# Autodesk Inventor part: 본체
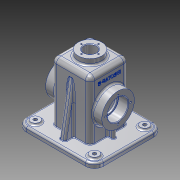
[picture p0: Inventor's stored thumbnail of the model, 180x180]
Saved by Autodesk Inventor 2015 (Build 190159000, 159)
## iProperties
Created: 2016-02
Part Number: 본체
Material: 알루미늄 6061
Document SubType Name: Modeling
Designer: Administrator
Density: 2.7 g/cm^3
Appearance: 알루미늄 - 평지
Mass: 783.394 g
Surface Area: 909.509 cm^2
Volume: 290.146 cm^3
Author: Administrator
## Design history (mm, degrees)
sketch "스케치1"
  geometry: L1 (-65, -57.5)-(65, -57.5); L2 (65, -57.5)-(65, 57.5); L3 (65, 57.5)-(-65, 57.5); L4 (-65, 57.5)-(-65, -57.5); 3 further points
  constraints: 8 end point, 2 midpoint, 2 parallel, 1 horizontal, 1 horizontal alignment, 1 perpendicular, 1 vertical alignment
  dimensions: "d0" = 130 distance of L2.end L3.end; "d1" = 115 distance of L1.end L2.end
extrude "돌출1" new body sketch "스케치1" distance "d2" = 8; taper "d3" = 0 deg
sketch "스케치2"
  geometry: L1 (-60, -52.5)-(60, -52.5); L2 (60, -52.5)-(60, 52.5); L3 (60, 52.5)-(-60, 52.5); L4 (-60, 52.5)-(-60, -52.5); 3 further points
  constraints: 8 end point, 2 midpoint, 2 parallel, 1 horizontal, 1 horizontal alignment, 1 perpendicular, 1 vertical alignment
  dimensions: "d4" = 105 distance of L3.end L1.start; "d5" = 120 distance of L2.end L3.end
extrude "돌출2" join sketch "스케치2" distance "d6" = 2; taper "d7" = 0 deg
sketch "스케치3"
  geometry: L1 (-32.5, -32.5)-(32.5, -32.5); L2 (32.5, -32.5)-(32.5, 32.5); L3 (32.5, 32.5)-(-32.5, 32.5); L4 (-32.5, 32.5)-(-32.5, -32.5); 3 further points
  constraints: 8 end point, 2 midpoint, 2 parallel, 1 horizontal, 1 horizontal alignment, 1 perpendicular, 1 vertical alignment
  dimensions: "d8" = 65 distance of L2.end L3.end; "d9" = 65 distance of L1.end L2.end
extrude "돌출3" join sketch "스케치3" distance "d10" = 100; taper "d11" = 0 deg
sketch "스케치4"
  geometry: L1 (27.5, -27.5)-(-27.5, -27.5); L2 (-27.5, -27.5)-(-27.5, 27.5); L3 (-27.5, 27.5)-(27.5, 27.5); L4 (27.5, 27.5)-(27.5, -27.5); 3 further points
  constraints: 8 end point, 2 midpoint, 2 parallel, 1 horizontal, 1 horizontal alignment, 1 perpendicular, 1 vertical alignment
  dimensions: "d12" = 55 distance of L1.end L2.end; "d13" = 55 distance of L2.end L3.end
extrude "돌출4" cut sketch "스케치4" distance "d14" = 105; taper "d15" = 0 deg
sketch "스케치5"
  geometry: C1 r 20 at (0, 0); 1 further point
  constraints: 1 centre point, 1 coincident
  dimensions: "d16" = 40 diameter of C1
extrude "돌출5" join sketch "스케치5" distance "d17" = 10; taper "d18" = 0 deg
hole "구멍1" diameter "d21" = 21; stored, may be unused: countersink angle "d25" = 90 deg, drill point angle "d27" = 118 deg; dims "d19" = 10, "d20" = 10, "d22" = 6, "d23" = 4, "d24" = 2, "d26" = 8
sketch "스케치7"
  geometry: C1 r 10.5 at (0, 0) reference; C2 r 20 at (0, 0) reference; 5 further points
  constraints: 2 horizontal alignment, 2 vertical alignment
  dimensions: "d28" = 14.5 distance of point (-14.5, 0) point (0, 0); "d29" = 14.5 distance of point (0, 0) point (0, 14.5); "d30" = 14.5 distance of point (0, 0) point (14.5, 0); "d31" = 14.5 distance of point (0, 0) point (0, -14.5)
hole "구멍2" sketch "스케치7" at (-14.5, 0), (0, 14.5), (14.5, 0), (0, -14.5) diameter "d32" = 2.459; stored, may be unused: countersink angle "d36" = 90 deg, drill point angle "d38" = 118 deg; dims "d33" = 7, "d34" = 4, "d35" = 2, "d37" = 9
fillet "모깎기1" dims "d43" = 15
sketch "스케치9"
  geometry: L1 (-50, 57.5)-(50, 57.5) reference; L2 (65, 42.5)-(65, -42.5) reference; L3 (50, -57.5)-(-50, -57.5) reference; L4 (-65, -42.5)-(-65, 42.5) reference; L5 (-27.5, 27.5)-(-27.5, -27.5) reference; L6 (-27.5, -27.5)-(27.5, -27.5) reference; L7 (27.5, -27.5)-(27.5, 27.5) reference; L8 (27.5, 27.5)-(-27.5, 27.5) reference; L9 (-32.5, -32.5)-(-32.5, 32.5) reference; L10 (-32.5, 32.5)-(32.5, 32.5) reference; L11 (32.5, 32.5)-(32.5, -32.5) reference; L12 (32.5, -32.5)-(-32.5, -32.5) reference; C1 r 7.5 at (-50, 42.5); C2 r 7.5 at (50, 42.5); C3 r 7.5 at (50, -42.5); C4 r 7.5 at (-50, -42.5); A1 r 15 centre (-50, 42.5) between (-50, 57.5) and (-65, 42.5) reference; A2 r 15 centre (50, 42.5) between (65, 42.5) and (50, 57.5) reference; A3 r 15 centre (50, -42.5) between (50, -57.5) and (65, -42.5) reference; A4 r 15 centre (-50, -42.5) between (-65, -42.5) and (-50, -57.5) reference; 1 further point
  constraints: 4 centre point, 4 coincident
  dimensions: "d44" = 15 diameter of C1; "d45" = 15 diameter of C2; "d46" = 15 diameter of C3; "d47" = 15 diameter of C4
extrude "돌출6" join sketch "스케치9" distance "d48" = 3; taper "d49" = 0 deg
hole "구멍3" diameter "d52" = 6; stored, may be unused: countersink angle "d56" = 90 deg, drill point angle "d58" = 118 deg; dims "d50" = 10, "d51" = 10, "d53" = 7, "d54" = 4, "d55" = 2, "d57" = 9
sketch "스케치10"
  geometry: L1 (10, -20)-(8, -20) reference; L2 (8, -20)-(8, -25) reference; L3 (8, -25)-(0, -25) reference; L4 (0, -25)-(0, 0) reference; L5 (0, 0)-(0, 65) reference; L6 (0, 65)-(0, 90) reference; L7 (0, 90)-(8, 90) reference; L8 (8, 90)-(8, 85) reference; L9 (8, 85)-(10, 85) reference; L10 (10, 85)-(10, -20) reference; L11 (0, 0)-(-100, 0) reference; L12 (-100, 0)-(-100, 65) reference; L13 (-100, 65)-(0, 65) reference; C1 r 27.5 at (-45, 32.5); 2 further points
  constraints: 1 centre point, 1 horizontal alignment, 1 midpoint
  dimensions: "d59" = 55 diameter of C1; "d60" = 55 distance from line of L10 C1.centre
extrude "돌출7" join sketch "스케치10" distance "d61" = 15; taper "d62" = 0 deg
sketch "스케치11"
  geometry: L1 (45, 35.429)-(42, 35.429) reference; L2 (42, 35.429)-(42, 40.842) reference; L3 (42, 40.842)-(55, 40.842) reference; L4 (55, 40.842)-(55, -40.842) reference; L5 (55, -40.842)-(42, -40.842) reference; L6 (42, -40.842)-(42, -35.429) reference; L7 (42, -35.429)-(45, -35.429) reference; L8 (45, -35.429)-(45, 35.429) reference; L9 (53, 52.5)-(55, 52.5) reference; L10 (55, 52.5)-(55, 44.158) reference; L11 (55, 44.158)-(42, 44.158) reference; L12 (42, 44.158)-(42, 49.571) reference; L13 (42, 49.571)-(45, 49.571) reference; L14 (45, 49.571)-(45, 57.5) reference; L15 (45, 57.5)-(53, 57.5) reference; L16 (53, 57.5)-(53, 52.5) reference; L17 (55, -52.5)-(53, -52.5) reference; L18 (53, -52.5)-(53, -57.5) reference; L19 (53, -57.5)-(45, -57.5) reference; L20 (45, -57.5)-(45, -49.571) reference; L21 (45, -49.571)-(42, -49.571) reference; L22 (42, -49.571)-(42, -44.158) reference; L23 (42, -44.158)-(55, -44.158) reference; L24 (55, -44.158)-(55, -52.5) reference; C1 r 27.5 at (0, 0) reference; C2 r 17.5 at (0, 0); 1 further point
  constraints: 1 centre point, 1 coincident
  dimensions: "d63" = 35 diameter of C2
extrude "돌출8" cut sketch "스케치11" distance "d64" = 17; taper "d65" = 0 deg
sketch "스케치12"
  geometry: L1 (55, -52.5)-(53, -52.5) reference; L2 (53, -52.5)-(53, -57.5) reference; L3 (53, -57.5)-(45, -57.5) reference; L4 (45, -57.5)-(45, -32.5) reference; L5 (45, -32.5)-(-55, -32.5) reference; L6 (-55, -32.5)-(-55, 32.5) reference; L7 (-55, 32.5)-(45, 32.5) reference; L8 (45, 32.5)-(45, 57.5) reference; L9 (45, 57.5)-(53, 57.5) reference; L10 (53, 57.5)-(53, 52.5) reference; L11 (53, 52.5)-(55, 52.5) reference; L12 (55, 52.5)-(55, -52.5) reference; C1 r 17.5 at (0, 0) reference; C2 r 15 at (0, 0); 1 further point
  constraints: 1 centre point, 1 coincident
  dimensions: "d66" = 30 diameter of C2
extrude "돌출9" cut sketch "스케치12" distance "d67" = 4; taper "d68" = 0 deg
sketch "스케치13"
  geometry: L1 (45, 35.429)-(42, 35.429) reference; L2 (42, 35.429)-(42, 40.842) reference; L3 (42, 40.842)-(55, 40.842) reference; L4 (55, 40.842)-(55, -40.842) reference; L5 (55, -40.842)-(42, -40.842) reference; L6 (42, -40.842)-(42, -35.429) reference; L7 (42, -35.429)-(45, -35.429) reference; L8 (45, -35.429)-(45, 35.429) reference; L9 (53, 52.5)-(55, 52.5) reference; L10 (55, 52.5)-(55, 44.158) reference; L11 (55, 44.158)-(42, 44.158) reference; L12 (42, 44.158)-(42, 49.571) reference; L13 (42, 49.571)-(45, 49.571) reference; L14 (45, 49.571)-(45, 57.5) reference; L15 (45, 57.5)-(53, 57.5) reference; L16 (53, 57.5)-(53, 52.5) reference; L17 (55, -52.5)-(53, -52.5) reference; L18 (53, -52.5)-(53, -57.5) reference; L19 (53, -57.5)-(45, -57.5) reference; L20 (45, -57.5)-(45, -49.571) reference; L21 (45, -49.571)-(42, -49.571) reference; L22 (42, -49.571)-(42, -44.158) reference; L23 (42, -44.158)-(55, -44.158) reference; L24 (55, -44.158)-(55, -52.5) reference; C1 r 17.5 at (0, 0) reference; C2 r 27.5 at (0, 0) reference; 5 further points
  constraints: 2 horizontal alignment, 2 vertical alignment
  dimensions: "d69" = 21 distance of C1.centre point (-21, 0); "d70" = 21 distance of C1.centre point (0, 21); "d71" = 21 distance of C1.centre point (21, 0); "d72" = 21 distance of point (0, -21) C1.centre
hole "구멍4" sketch "스케치13" at (-21, 0), (0, 21), (21, 0), (0, -21) diameter "d73" = 3.242; stored, may be unused: countersink angle "d77" = 90 deg, drill point angle "d79" = 118 deg; dims "d74" = 8, "d75" = 4, "d76" = 2, "d78" = 10
chamfer "모따기1" distance "d80" = 1; stored, may be unused: second distance "d81" = 2, angle "d82" = 45 deg
chamfer "모따기2" distance "d83" = 1; stored, may be unused: second distance "d84" = 2, angle "d85" = 45 deg
sketch "스케치14"
  geometry: L1 (-42.161, 38.278)-(-47.5, 8); L2 (-57.5, 8)-(-57.5, 0) reference; L3 (-42.5, 8)-(42.5, 8) reference; L4 (-32.5, 8)-(-32.5, 108) reference; 1 further point
  constraints: 2 end point, 1 horizontal alignment
  dimensions: "d88" = 10 distance from line of L2 L1.end; "d123" = 10 deg angle of L2 L1; "d124" = 9.66119 distance from line of L4 L1.start
feature "리브1" sketch "스케치14" dims "d90" = 1, "d91" = 10, "d92" = 0, "d93" = 0, "d94" = 1, "d95" = 1
fillet "모깎기2" dims "d96" = 3
fillet "모깎기3" dims "d97" = 3
fillet "모깎기4" dims "d98" = 3
fillet "모깎기5" dims "d99" = 3
sketch "스케치15"
  geometry: L1 (5, -35.5)-(5, -44.454) reference; L2 (2, -47.5)-(-2, -47.5) reference; L3 (-5, -44.454)-(-5, -35.5) reference; L4 (-8, -32.5)-(-32.5, -32.5) reference; L5 (-32.5, -32.5)-(-32.5, 32.5) reference; L6 (-32.5, 32.5)-(-8, 32.5) reference; L7 (-5, 35.5)-(-5, 44.454) reference; L8 (-2, 47.5)-(2, 47.5) reference; L9 (5, 44.454)-(5, 35.5) reference; L10 (8, 32.5)-(32.5, 32.5) reference; L11 (32.5, 32.5)-(32.5, -32.5) reference; L12 (32.5, -32.5)-(8, -32.5) reference; L13 (27.5, 27.5)-(-27.5, 27.5) reference; L14 (-27.5, 27.5)-(-27.5, -27.5) reference; L15 (-27.5, -27.5)-(27.5, -27.5) reference; L16 (27.5, -27.5)-(27.5, 27.5) reference; L17 (-50, 57.5)-(50, 57.5) reference; L18 (65, 42.5)-(65, -42.5) reference; L19 (50, -57.5)-(-50, -57.5) reference; L20 (-65, -42.5)-(-65, 42.5) reference; L21 (32.5, -3)-(42.5, -3); L22 (42.5, -3)-(42.5, 3); L23 (42.5, 3)-(32.5, 3); L24 (32.5, 3)-(32.5, -3); C1 r 3 at (50, 42.5) reference; C2 r 3 at (50, -42.5) reference; C3 r 3 at (-50, 42.5) reference; C4 r 3 at (-50, -42.5) reference; C5 r 7.5 at (50, -42.5) reference; C6 r 7.5 at (-50, 42.5) reference; C7 r 7.5 at (50, 42.5) reference; C8 r 7.5 at (-50, -42.5) reference; A1 r 3 centre (8, -35.5) between (8, -32.5) and (5, -35.5) reference; A2 r 3 centre (-8, -35.5) between (-5, -35.5) and (-8, -32.5) reference; A3 r 3 centre (-8, 35.5) between (-8, 32.5) and (-5, 35.5) reference; A4 r 3 centre (8, 35.5) between (5, 35.5) and (8, 32.5) reference; A5 r 15 centre (-50, 42.5) between (-50, 57.5) and (-65, 42.5) reference; A6 r 15 centre (50, 42.5) between (65, 42.5) and (50, 57.5) reference; A7 r 15 centre (50, -42.5) between (50, -57.5) and (65, -42.5) reference; A8 r 15 centre (-50, -42.5) between (-65, -42.5) and (-50, -57.5) reference; 6 further points; 4 other entities
  constraints: 8 end point, 2 parallel, 1 horizontal, 1 horizontal alignment, 1 midpoint, 1 perpendicular, 1 point on line, 4 other
  dimensions: "d101" = 6 distance of L21.end L22.end; "d104" = 15 distance between parallel lines of L16 L22
extrude "돌출10" join sketch "스케치15" stored distance "d102" = 4; taper "d103" = 0 deg
fillet "모깎기8" dims "d107" = 0.3
fillet "모깎기10" dims "d109" = 8
fillet "모깎기12" dims "d111" = 3
fillet "모깎기13" dims "d112" = 3
fillet "모깎기14" dims "d113" = 1
node "작업 평면1"
sketch "스케치16"
  geometry: L1 (-32.5, 108)-(-32.5, 9) reference; L2 (20, 118)-(-20, 118) reference; 3 further points
  constraints: 1 other
  dimensions: "d115" = 32.5 distance from line of point (0, 92) L1; "d116" = 26 distance from line of point (0, 92) L2
feature "엠보싱1" sketch "스케치16" dims "d8" = 65, "d9" = 65, "d117" = 0.5, "d118" = 0
fillet "모깎기15" dims "d119" = 10
fillet "모깎기17" dims "d125" = 8
fillet "모깎기18" dims "d126" = 3
fillet "모깎기19" dims "d127" = 3
fillet "모깎기21" dims "d129" = 3
node "솔리드1"
mirror "대칭1"
mirror "대칭2"
mirror "대칭3"
mirror "대칭4"
mirror "대칭5"
node "절단 모서리 투영1"
node "절단 모서리 투영3"
node "절단 모서리 투영4"
node "절단 모서리 투영5"
node "절단 모서리 투영6"
node "절단 모서리 투영7"
node "절단 모서리 투영8"
other parameters: "d114" = 98.5
